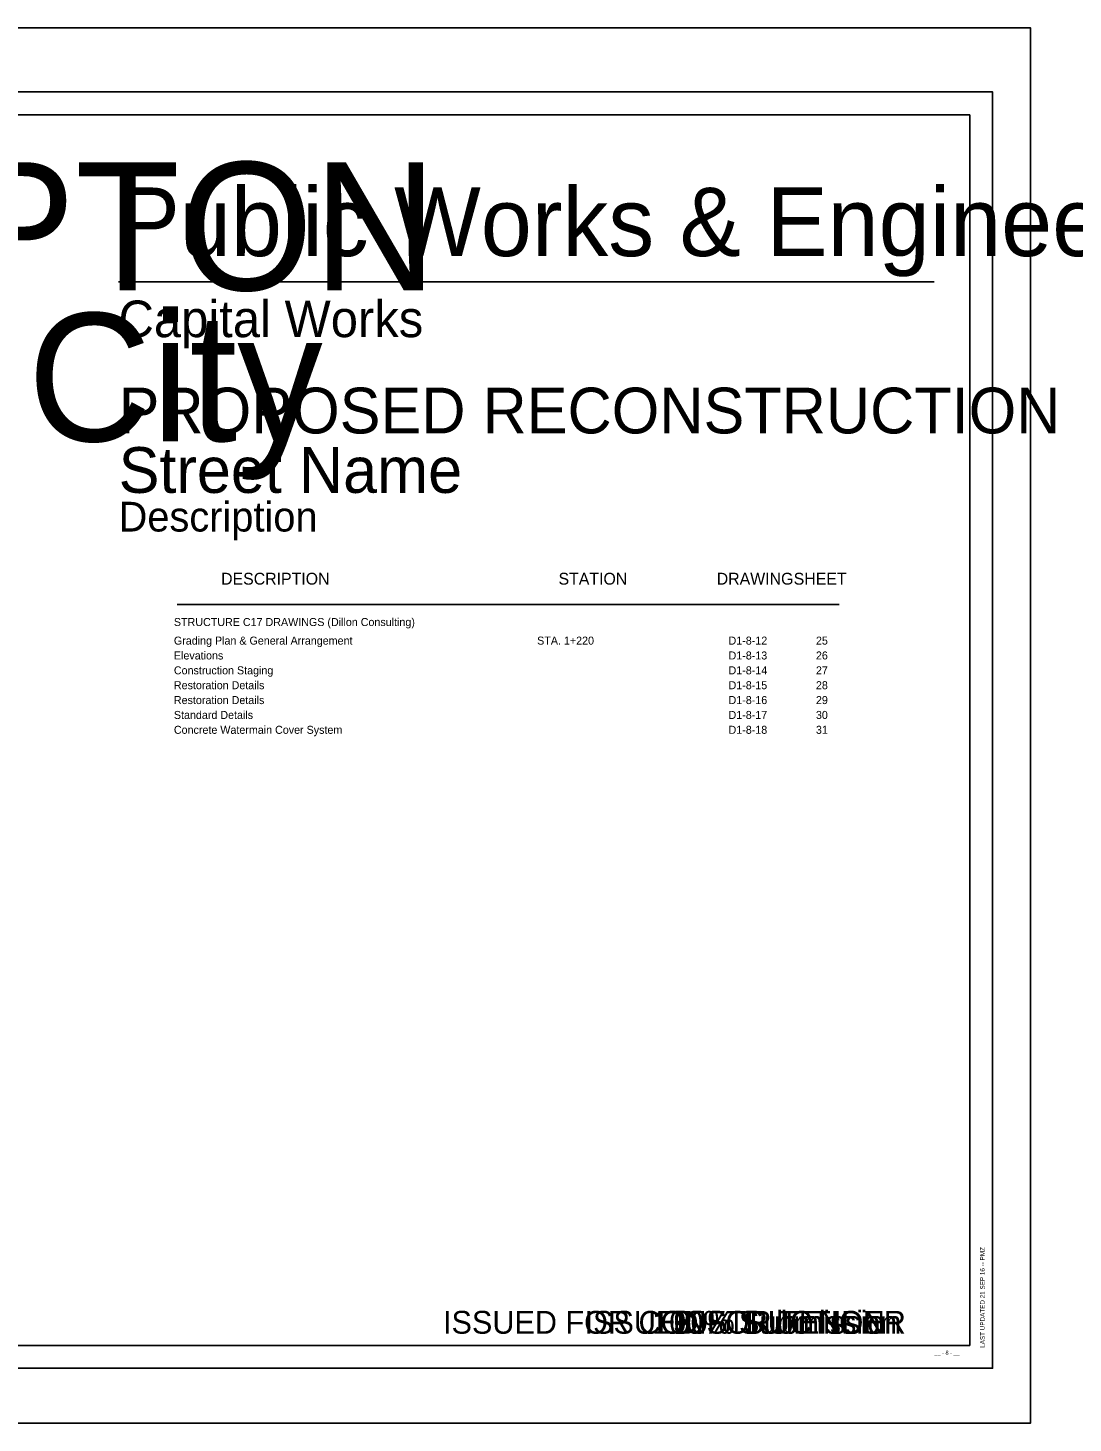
# Model space of a CAD drawing. Extents: x 589136 to 589858, y 4822787 to 4823225.
# Drawn here: x 589385.1 to 589613.5, y 4822849.6 to 4823154.6 of the extents above; entities that cross this region are included whole.
import ezdxf

# ---------------------------------------------------------------- set-up
doc = ezdxf.new("R2010")
doc.units = 0
for name, color, linetype in [('-PRINT FULLSIZE', 7, 'Continuous'), ('-PRINT HALFSIZE', 7, 'Continuous'), ('ENG_BORDER', 7, 'Continuous'), ('ENG_ISSUED_100 PERCENT', 7, 'Continuous'), ('ENG_ISSUED_30 PERCENT', 7, 'Continuous'), ('ENG_ISSUED_60 PERCENT', 7, 'Continuous'), ('ENG_ISSUED_90 PERCENT', 7, 'Continuous'), ('ENG_ISSUED_CONSTRUCTION', 7, 'Continuous'), ('ENG_ISSUED_TENDER', 7, 'Continuous'), ('ENG_TITLEBLOCK', 7, 'Continuous'), ('ENG_TX_BORDER', 7, 'Continuous'), ('ENG_TX_TITLEBLOCK', 7, 'Continuous')]:
    doc.layers.add(name, color=color, linetype=linetype)

msp = doc.modelspace()

# ---------------------------------------------------------------- linework, layer by layer
at = {"layer": '-PRINT FULLSIZE'}
msp.add_lwpolyline([(589157.2, 4822849.64), (589604.23, 4822849.64), (589604.23, 4823154.64), (589157.2, 4823154.64)], close=True, dxfattribs=at)
at = {"layer": '-PRINT HALFSIZE'}
msp.add_lwpolyline([(589187, 4823140.63), (589595.92, 4823140.63), (589595.92, 4822861.63), (589187, 4822861.63)], close=True, dxfattribs=at)
at = {"layer": 'ENG_BORDER'}
msp.add_lwpolyline([(589204.72, 4822866.63), (589590.92, 4822866.63), (589590.92, 4823135.63), (589204.72, 4823135.63)], close=True, dxfattribs=at)
at = {"layer": 'ENG_TITLEBLOCK'}
for p, q in [((589404.94, 4823099.11), (589583.13, 4823099.11)), ((589417.7, 4823028.58), (589562.4, 4823028.58))]:
    msp.add_line(p, q, dxfattribs=at)

# ---------------------------------------------------------------- texts
at = {"layer": '-PRINT HALFSIZE'}
msp.add_text('LAST UPDATED 21 SEP 16 -- PMZ', height=1, rotation=90, dxfattribs=at).set_placement((589594.2, 4822866.1))
at = {"layer": 'ENG_ISSUED_100 PERCENT'}
msp.add_text('100% Submission', height=5, dxfattribs=at).set_placement((589521.54, 4822869.17))
at = {"layer": 'ENG_ISSUED_30 PERCENT'}
msp.add_text('30% Submission', height=5, dxfattribs=at).set_placement((589526.2, 4822869.17))
at = {"layer": 'ENG_ISSUED_60 PERCENT'}
msp.add_text('60% Submission', height=5, dxfattribs=at).set_placement((589526.2, 4822869.17))
at = {"layer": 'ENG_ISSUED_90 PERCENT'}
msp.add_text('90% Submission', height=5, dxfattribs=at).set_placement((589526.2, 4822869.17))
at = {"layer": 'ENG_ISSUED_CONSTRUCTION'}
msp.add_text('ISSUED FOR CONSTRUCTION', height=5, dxfattribs=at).set_placement((589475.83, 4822869.17))
at = {"layer": 'ENG_ISSUED_TENDER'}
msp.add_text('ISSUED FOR TENDER', height=5, dxfattribs=at).set_placement((589506.76, 4822869.17))
at = {"layer": 'ENG_TX_BORDER'}
msp.add_text('__ - 8 - __', height=0.875, dxfattribs=at).set_placement((589583.22, 4822864.6))
at = {"layer": 'ENG_TX_TITLEBLOCK'}
for s, height, p in [('BRAMPTON', 28, (589262.32, 4823097.28)), ('Public Works & Engineering', 15, (589404.94, 4823104.75)), ('Flower City', 28, (589262.32, 4823064.28)), ('Capital Works', 8, (589404.93, 4823087.03)), ('PROPOSED RECONSTRUCTION', 10, (589404.95, 4823065.99)), ('Street Name', 10, (589404.95, 4823052.99)), ('Description', 6.5, (589404.94, 4823044.54)), ('DESCRIPTION', 2.592, (589427.34, 4823032.93)), ('STATION', 2.592, (589501.07, 4823032.93)), ('DRAWING', 2.592, (589535.64, 4823032.93)), ('SHEET', 2.592, (589552.46, 4823032.93)), ('STRUCTURE C17 DRAWINGS (Dillon Consulting)', 1.75, (589417.02, 4823023.88)), ('Grading Plan & General Arrangement', 1.75, (589417.02, 4823019.82)), ('STA. 1+220', 1.75, (589496.4, 4823019.82)), ('D1-8-12', 1.75, (589538.22, 4823019.82)), ('25', 1.75, (589557.32, 4823019.82)), ('Elevations', 1.75, (589417.02, 4823016.57)), ('D1-8-13', 1.75, (589538.22, 4823016.57)), ('26', 1.75, (589557.32, 4823016.57)), ('Construction Staging', 1.75, (589417.02, 4823013.32)), ('D1-8-14', 1.75, (589538.22, 4823013.32)), ('27', 1.75, (589557.32, 4823013.32)), ('Restoration Details', 1.75, (589417.02, 4823010.07)), ('D1-8-15', 1.75, (589538.22, 4823010.07)), ('28', 1.75, (589557.32, 4823010.07)), ('Restoration Details', 1.75, (589417.02, 4823006.82)), ('D1-8-16', 1.75, (589538.22, 4823006.82)), ('29', 1.75, (589557.32, 4823006.82)), ('Standard Details', 1.75, (589417.02, 4823003.57)), ('D1-8-17', 1.75, (589538.22, 4823003.57)), ('30', 1.75, (589557.32, 4823003.57)), ('Concrete Watermain Cover System', 1.75, (589417.02, 4823000.32)), ('D1-8-18', 1.75, (589538.22, 4823000.32)), ('31', 1.75, (589557.32, 4823000.32))]:
    msp.add_text(s, height=height, dxfattribs=at).set_placement(p)

doc.saveas('drawing.dxf')
